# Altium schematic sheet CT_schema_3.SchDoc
size 368 x 245 mm
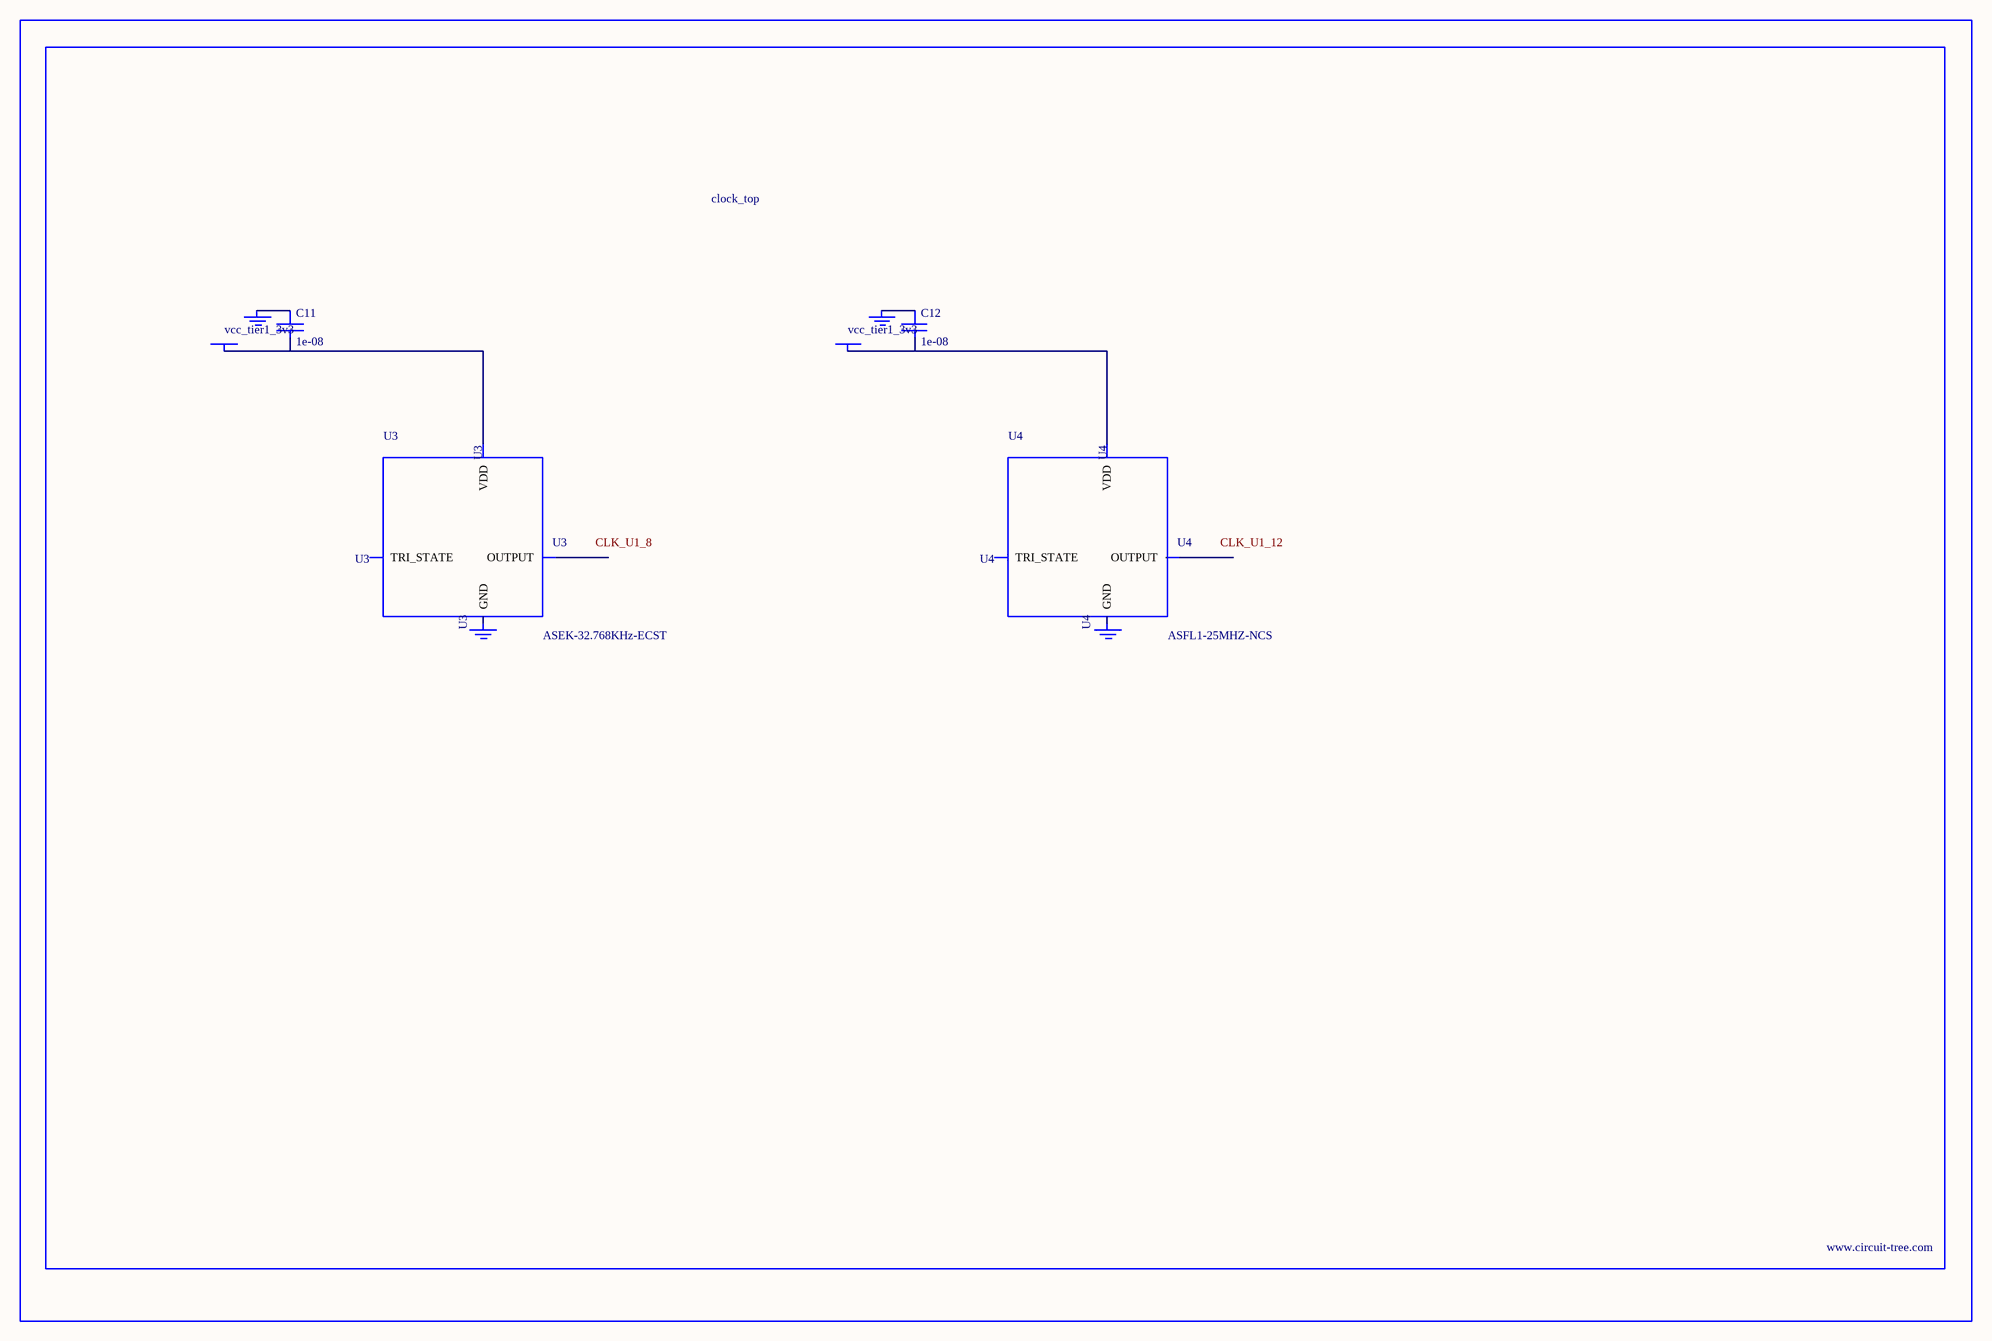
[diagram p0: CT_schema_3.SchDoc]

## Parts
BORDER2  (no value)
C11  1e-08  [C0402]
C12  1e-08  [C0402]
GND_INSTANCE_2_0  (no value)
GND_INSTANCE_2_1  (no value)
GND_INSTANCE_2_2  (no value)
GND_INSTANCE_2_3  (no value)
POWER_INSTANCE_2_0  vcc_tier1_3v3
POWER_INSTANCE_2_1  vcc_tier1_3v3
U3  ASEK-32.768KHz-ECST  [ASEK]
U4  ASFL1-25MHZ-NCS  [ASFL1]

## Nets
NetC11_1: C11.1 GND_INSTANCE_2_0.0(GND)
NetC11_2: C11.2 POWER_INSTANCE_2_0.0(PWR) U3.4(VDD)
NetC12_1: C12.1 GND_INSTANCE_2_2.0(GND)
NetC12_2: C12.2 POWER_INSTANCE_2_1.0(PWR) U4.4(VDD)

Not connected (* = marked no-connect by the designer): GND_INSTANCE_2_1 0(GND); GND_INSTANCE_2_3 0(GND); U3 1(TRI_STATE) 2(GND) 3(OUTPUT); U4 1(TRI_STATE) 2(GND) 3(OUTPUT)

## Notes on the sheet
- Labels drawn without touching a wire or pin: CLK_U1_8, CLK_U1_12

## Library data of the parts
BORDER2 = BORDER_PAGE2
C11 C12 = C0402C103K3RAC
GND_INSTANCE_2_0-GND_INSTANCE_2_3 = GND
POWER_INSTANCE_2_0 POWER_INSTANCE_2_1 = PWR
